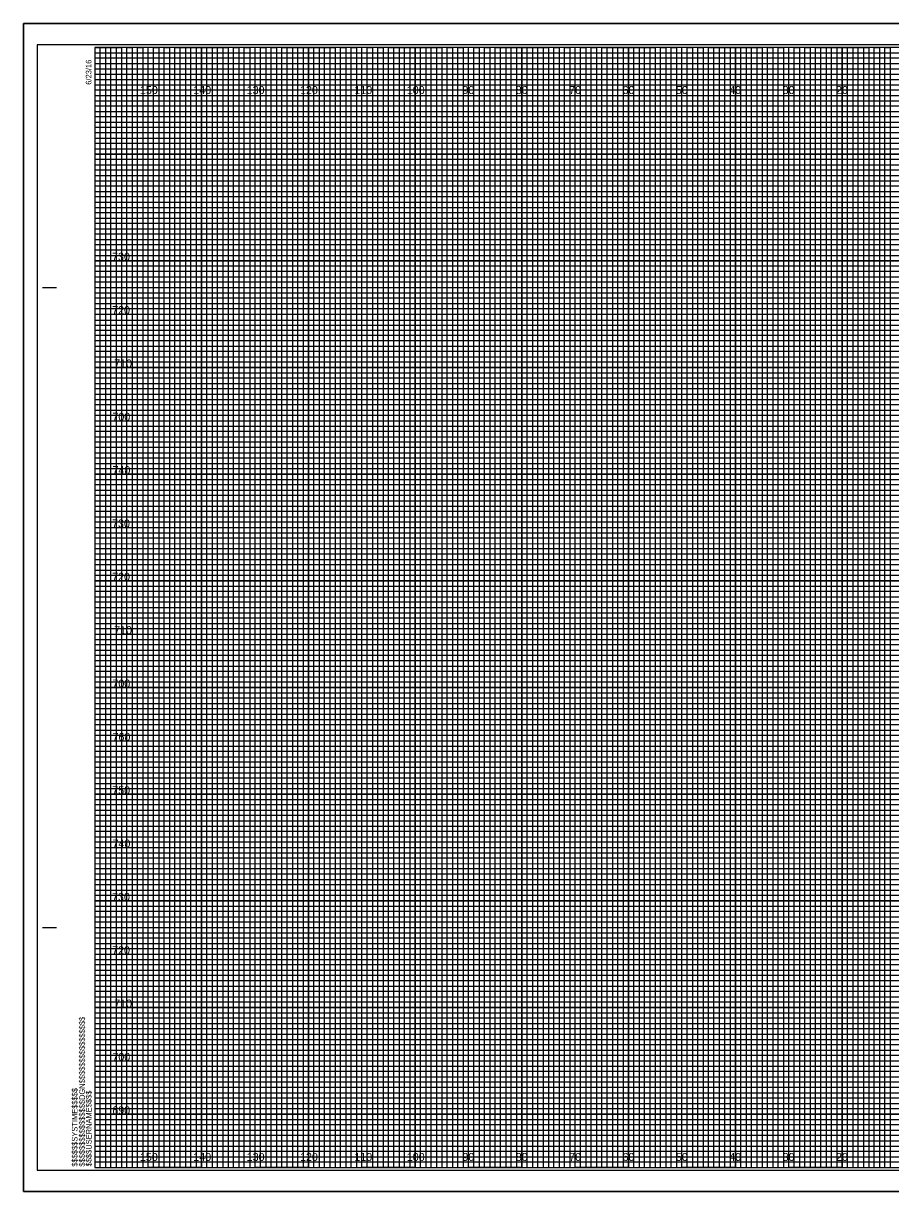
# Model space of a CAD drawing. Extents: x -397 to 323, y -4 to 654.
# Drawn here: x -13.4 to 149.1, y 215.5 to 434.5 of the extents above; entities that cross this region are included whole.
import ezdxf

# ---------------------------------------------------------------- set-up
doc = ezdxf.new("R2010")
doc.units = 0
for name, color, linetype in [('Default', 7, 'Continuous'), ('Prop XS Elevation Labels', 7, 'Continuous'), ('Prop XS Offset Labels', 7, 'Continuous'), ('Sheet Cross Section CELL', 7, 'Continuous'), ('Sheet Cross Section Grid Major CELL', 7, 'Continuous'), ('Sheet Cross Section Grid Middle CELL', 7, 'Continuous'), ('Sheet Cross Section Grid Minor 1 CELL', 7, 'Continuous'), ('Sheet Cross Section Grid Minor 2 CELL', 7, 'Continuous'), ('Sheet Cutting Line CELL', 7, 'Continuous'), ('Sheet DOT Grid CELL', 7, 'Continuous'), ('Sheet Plot Border Inside CELL', 7, 'Continuous'), ('Sheet Plot Border Outside CELL', 7, 'Continuous')]:
    doc.layers.add(name, color=color, linetype=linetype)

msp = doc.modelspace()

# ---------------------------------------------------------------- linework, layer by layer
at = {"layer": 'Default'}
msp.add_lwpolyline([(323.3, 215.5), (-13.4, 215.5), (-13.4, 434.5), (323.3, 434.5)], close=True, dxfattribs=at)
at = {"layer": 'Sheet Cross Section CELL'}
for p, q in [((-9.8, 385), (-7.3, 385)), ((-9.7, 385), (-7.2, 385)), ((-9.8, 265), (-7.3, 265)), ((-9.7, 265), (-7.2, 265)), ((0, 220), (0, 220)), ((0, 220), (0, 220)), ((0, 220), (0, 220)), ((0, 220), (0, 220)), ((0, 220), (0, 220)), ((0, 220), (0, 220)), ((0, 220), (0, 220))]:
    msp.add_line(p, q, dxfattribs=at)
msp.add_lwpolyline([(320, 430), (0, 430), (0, 220), (320, 220)], close=True, dxfattribs=at)
at = {"layer": 'Sheet Cross Section Grid Major CELL'}
for p, q in [((10, 430), (0, 430)), ((10, 220), (10, 430)), ((30, 430), (20, 430)), ((20, 430), (20, 220)), ((30, 220), (30, 430)), ((50, 430), (40, 430)), ((40, 430), (40, 220)), ((50, 220), (50, 430)), ((70, 430), (60, 430)), ((60, 430), (60, 220)), ((70, 220), (70, 430)), ((90, 430), (80, 430)), ((80, 430), (80, 220)), ((90, 220), (90, 430)), ((110, 430), (100, 430)), ((100, 430), (100, 220)), ((110, 220), (110, 430)), ((130, 430), (120, 430)), ((120, 430), (120, 220)), ((130, 220), (130, 430)), ((150, 430), (140, 430)), ((140, 430), (140, 220)), ((20, 220), (10, 220)), ((40, 220), (30, 220)), ((60, 220), (50, 220)), ((80, 220), (70, 220)), ((100, 220), (90, 220)), ((120, 220), (110, 220)), ((140, 220), (130, 220))]:
    msp.add_line(p, q, dxfattribs=at)
for points in [[(0, 420), (320, 420), (320, 410), (0, 410)], [(0, 400), (320, 400), (320, 390), (0, 390)], [(0, 380), (320, 380), (320, 370), (0, 370)], [(0, 360), (320, 360), (320, 350), (0, 350)], [(0, 340), (320, 340), (320, 330), (0, 330)], [(0, 320), (320, 320), (320, 310), (0, 310)], [(0, 300), (320, 300), (320, 290), (0, 290)], [(0, 280), (320, 280), (320, 270), (0, 270)], [(0, 260), (320, 260), (320, 250), (0, 250)], [(0, 240), (320, 240), (320, 230), (0, 230)]]:
    msp.add_lwpolyline(points, dxfattribs=at)
at = {"layer": 'Sheet Cross Section Grid Middle CELL'}
for points in [[(0, 430), (5, 430), (5, 220), (15, 220), (15, 430), (25, 430), (25, 220), (35, 220), (35, 430), (45, 430), (45, 220), (55, 220), (55, 430), (65, 430), (65, 220), (75, 220), (75, 430), (85, 430), (85, 220), (95, 220), (95, 430), (105, 430), (105, 220), (115, 220), (115, 430), (125, 430), (125, 220), (135, 220), (135, 430), (145, 430), (145, 220), (155, 220)], [(0, 425), (275, 425)], [(0, 405), (320, 405), (320, 415), (0, 415)], [(0, 385), (320, 385), (320, 395), (0, 395)], [(0, 365), (320, 365), (320, 375), (0, 375)], [(0, 345), (320, 345), (320, 355), (0, 355)], [(0, 325), (320, 325), (320, 335), (0, 335)], [(0, 305), (320, 305), (320, 315), (0, 315)], [(0, 285), (320, 285), (320, 295), (0, 295)], [(0, 265), (320, 265), (320, 275), (0, 275)], [(0, 245), (320, 245), (320, 255), (0, 255)], [(0, 225), (320, 225), (320, 235), (0, 235)]]:
    msp.add_lwpolyline(points, dxfattribs=at)
at = {"layer": 'Sheet Cross Section Grid Minor 1 CELL'}
for p, q in [((0, 429), (260, 429)), ((260, 427.98), (0, 427.98)), ((0, 427.98), (0, 427)), ((0, 427), (260, 427)), ((260, 425.89), (0, 425.89)), ((0, 425.89), (0, 424)), ((0, 424), (320, 424))]:
    msp.add_line(p, q, dxfattribs=at)
for points in [[(0, 423), (270, 423), (320, 423), (320, 422), (0, 422)], [(0, 421), (320, 421), (320, 419), (0, 419)], [(0, 418), (320, 418), (320, 417), (0, 416.98)], [(0, 416), (320, 416), (320, 414), (0, 414)], [(0, 413), (320, 413), (320, 412), (0, 412)], [(0, 411), (320, 411), (320, 409), (0, 409)], [(0, 408), (320, 408), (320, 407), (0, 407)], [(0, 406), (320, 406), (320, 404), (0, 404)], [(0, 403), (320, 403), (320, 402), (0, 402)], [(0, 401), (320, 401), (320, 399), (0, 399)], [(0, 398), (320, 398), (320, 397), (0, 397)], [(0, 396), (320, 396), (320, 393.95), (320, 393), (320, 392), (0, 392)], [(0, 394), (320, 394), (320, 393), (0, 393)], [(0, 391), (320, 391), (320, 389), (0, 389.03)], [(0, 389.03), (320, 389), (320, 388), (0, 388)], [(0, 387), (320, 387), (320, 386), (0, 386)], [(0, 384), (320, 384), (320, 383), (0, 383)], [(0, 382), (320, 382), (320, 381), (0, 381)], [(-0.07, 378.89), (320, 378.89), (320, 377.88), (-0.07, 377.88)], [(0, 377), (320, 377), (320, 376), (0, 376)], [(0, 374), (320, 374), (320, 373), (0, 373)], [(0, 372), (320, 372), (320, 371), (0, 371)], [(0, 369), (320, 369), (320, 368), (0, 368)], [(0, 367), (320, 367), (320, 366), (0, 366)], [(0, 364), (320, 364), (320, 363), (0, 363)], [(0, 362), (320, 362), (320, 361), (0, 361)], [(0, 359), (320, 359), (319.99, 357.98), (0, 358)], [(0, 357), (320, 357), (320, 356), (0, 356)], [(0, 354), (320, 354), (320, 353), (0, 353)], [(0, 352), (320, 352), (320, 351), (0, 351)], [(0, 349), (320, 349), (320, 348), (0, 348)], [(0, 347), (320, 347), (320, 346), (0, 346)], [(0, 344), (320, 344), (320, 343), (0, 343)], [(0, 342), (320, 342), (320, 341), (0, 341)], [(0, 339), (320, 339), (320, 338), (0, 338)], [(0, 336.99), (320.07, 336.91), (320, 336), (0, 336)], [(0, 334), (320, 334), (320, 333), (0, 333)], [(0, 332), (320, 332), (320, 331), (0, 331)], [(0, 329), (320, 329), (320, 328), (0, 328)], [(0, 327), (320, 327), (320, 326), (0, 326)], [(0, 324), (320, 324), (320, 323), (0, 323)], [(0, 322), (320, 322), (320, 321), (0, 321)], [(0, 319), (320, 319), (320, 318), (0, 318)], [(0, 317), (320, 317), (320, 316), (0, 316)], [(0, 314), (320, 314), (320, 313), (0, 313)], [(0, 312), (320, 312), (320, 311), (0, 311)], [(0, 309), (320, 309), (320, 308), (0, 308)], [(0, 307), (320, 307), (320, 306), (0, 306)], [(0, 304), (320, 304), (320, 303), (0, 303)], [(0, 302), (320, 302), (320, 301), (0, 301)], [(0, 299), (320, 299), (319.99, 297.98), (0, 298)], [(0, 297), (320, 297), (320, 296), (0, 296)], [(0, 294), (320, 294), (320, 293), (0, 293)], [(0, 292), (320, 292), (320, 291), (0, 291)], [(0, 289), (320, 289), (320, 288), (0, 288)], [(0, 287), (320, 287), (320, 286), (0, 286)], [(0, 284), (320, 284), (320, 283), (0, 283)], [(0, 282), (320, 282), (320, 281), (0, 281)], [(0, 279), (320, 279), (320, 278), (0, 278)], [(0, 276.99), (320.07, 276.91), (320, 276), (0, 276)], [(0, 274), (320, 274), (320, 273), (0, 273)], [(0, 272), (320, 272), (320, 271), (0, 271)], [(0, 269), (320, 269), (320, 268), (0, 268)], [(0, 267), (320, 267), (320, 266), (0, 266)], [(0, 264), (320, 264), (320, 263), (0, 263)], [(0, 262), (320, 262), (320, 261), (0, 261)], [(0, 259), (320, 259), (320, 258), (0, 258)], [(0, 257), (320, 257), (320, 256), (0, 256)], [(0, 254), (320, 254), (320, 253), (0, 253)], [(0, 252), (320, 252), (320, 251), (0, 251)], [(0, 249), (320, 249), (320, 248), (0, 248)], [(0, 247), (320, 247), (320, 246), (0, 246)], [(0, 244), (320, 244), (320, 243), (0, 243)], [(0, 242), (320, 242), (320, 241), (0, 241)], [(0, 239), (320, 239), (320, 238), (0, 238)], [(0, 237), (320, 237), (320, 236), (0, 236)], [(0, 234), (320, 234), (320, 233), (0, 233)], [(0, 232), (320, 232), (320, 231), (0, 231)], [(0, 229), (320, 229), (320, 228), (0, 228)], [(0, 227), (320, 227), (320, 226), (0, 226)], [(0, 224), (320, 224), (320, 223), (0, 223)], [(0, 222), (320, 222), (320, 221), (0, 221)]]:
    msp.add_lwpolyline(points, dxfattribs=at)
at = {"layer": 'Sheet Cross Section Grid Minor 2 CELL'}
for points in [[(0, 220), (1, 220), (1, 430), (2, 430), (2, 220)], [(2, 220), (3, 220), (3, 430), (4, 430), (4, 220)], [(5, 220), (6, 220), (6, 430), (7, 430), (7, 220)], [(7, 220), (8, 220), (8, 430), (9, 430), (9, 220)], [(10, 220), (11, 220), (11, 430), (12, 430), (12, 220)], [(12, 220), (13, 220), (13, 430), (14, 430), (14, 220)], [(15, 220), (16, 220), (16, 430), (17, 430), (17, 220)], [(17, 220), (18, 220), (18, 430), (19, 430), (19, 220)], [(20, 220), (21, 220), (21, 430), (22, 430), (22, 220)], [(22, 220), (23, 220), (23, 430), (24, 430), (24, 220)], [(25, 220), (26, 220), (26, 430), (27, 430), (27, 220)], [(27, 220), (28, 220), (28, 430), (29, 430), (29, 220)], [(30, 220), (31, 220), (31, 430), (32, 430), (32, 220)], [(32, 220), (33, 220), (33, 430), (34, 430), (34, 220)], [(35, 220), (36, 220), (36, 430), (37, 430), (37, 220)], [(37, 220), (38, 220), (38, 430), (39, 430), (39, 220)], [(40, 220), (41, 220), (41, 430), (42, 430), (42, 220)], [(42, 220), (43, 220), (43, 430), (44, 430), (44, 220)], [(45, 220), (46, 220), (46, 430), (47, 430), (47, 220)], [(47, 220), (48, 220), (48, 430), (49, 430), (49, 220)], [(50, 220), (51, 220), (51, 430), (52, 430), (52, 220)], [(52, 220), (53, 220), (53, 430), (54, 430), (54, 220)], [(55, 220), (56, 220), (56, 430), (57, 430), (57, 220)], [(57, 220), (58, 220), (58, 430), (59, 430), (59, 220)], [(60, 220), (61, 220), (61, 430), (62, 430), (62, 220)], [(62, 220), (63, 220), (63, 430), (64, 430), (64, 220)], [(65, 220), (66, 220), (66, 430), (67, 430), (67, 220)], [(67, 220), (68, 220), (68, 430), (69, 430), (69, 220)], [(70, 220), (71, 220), (71, 430), (72, 430), (72, 220)], [(72, 220), (73, 220), (73, 430), (74, 430), (74, 220)], [(75, 220), (76, 220), (76, 430), (77, 430), (77, 220)], [(77, 220), (78, 220), (78, 430), (79, 430), (79, 220)], [(80, 220), (81, 220), (81, 430), (82, 430), (82, 220)], [(82, 220), (83, 220), (83, 430), (84, 430), (84, 220)], [(85, 220), (86, 220), (86, 430), (87, 430), (87, 220)], [(87, 220), (88, 220), (88, 430), (89, 430), (89, 220)], [(90, 220), (91, 220), (91, 430), (92, 430), (92, 220)], [(92, 220), (93, 220), (93, 430), (94, 430), (94, 220)], [(95, 220), (96, 220), (96, 430), (97, 430), (97, 220)], [(97, 220), (98, 220), (98, 430), (99, 430), (99, 220)], [(100, 220), (101, 220), (101, 430), (102, 430), (102, 220)], [(102, 220), (103, 220), (103, 430), (104, 430), (104, 220)], [(105, 220), (106, 220), (106, 430), (107, 430), (107, 220)], [(107, 220), (108, 220), (108, 430), (109, 430), (109, 220)], [(110, 220), (111, 220), (111, 430), (112, 430), (112, 220)], [(112, 220), (113, 220), (113, 430), (114, 430), (114, 220)], [(115, 220), (116, 220), (116, 430), (117, 430), (117, 220)], [(117, 220), (118, 220), (118, 430), (119, 430), (119, 220)], [(120, 220), (121, 220), (121, 430), (122, 430), (122, 220)], [(122, 220), (123, 220), (123, 430), (124, 430), (124, 220)], [(125, 220), (126, 220), (126, 430), (127, 430), (127, 220)], [(127, 220), (128, 220), (128, 430), (129, 430), (129, 220)], [(130, 220), (131, 220), (131, 430), (132, 430), (132, 220)], [(132, 220), (133, 220), (133, 430), (134, 430), (134, 220)], [(135, 220), (136, 220), (136, 430), (137, 430), (137, 220)], [(137, 220), (138, 220), (138, 430), (139, 430), (139, 220)], [(140, 220), (141, 220), (141, 430), (142, 430), (142, 220)], [(142, 220), (143, 220), (143, 430), (144, 430), (144, 220)], [(145, 220), (146, 220), (146, 430), (147, 430), (147, 220)], [(147, 220), (148, 220), (148, 430), (149, 430), (149, 220)]]:
    msp.add_lwpolyline(points, dxfattribs=at)
at = {"layer": 'Sheet Cutting Line CELL'}
for p, q in [((323.3, 434.5), (-13.4, 434.5)), ((-13.4, 434.5), (-13.4, 215.5)), ((-13.4, 215.5), (323.3, 215.5))]:
    msp.add_line(p, q, dxfattribs=at)
at = {"layer": 'Sheet DOT Grid CELL'}
for p, q in [((10, 220), (10, 430)), ((20, 220), (20, 430)), ((30, 220), (30, 430)), ((40, 220), (40, 430)), ((50, 220), (50, 430)), ((60, 220), (60, 430)), ((70, 220), (70, 430)), ((80, 220), (80, 430)), ((90, 220), (90, 430)), ((100, 220), (100, 430)), ((110, 220), (110, 430)), ((120, 220), (120, 430)), ((130, 220), (130, 430)), ((140, 220), (140, 430)), ((0, 420), (320, 420)), ((0, 410), (320, 410)), ((0, 400), (320, 400)), ((0, 390), (320, 390)), ((0, 380), (320, 380)), ((0, 370), (320, 370)), ((0, 360), (320, 360)), ((0, 350), (320, 350)), ((0, 340), (320, 340)), ((0, 330), (320, 330)), ((0, 320), (320, 320)), ((0, 310), (320, 310)), ((0, 300), (320, 300)), ((0, 290), (320, 290)), ((0, 280), (320, 280)), ((0, 270), (320, 270)), ((0, 260), (320, 260)), ((0, 250), (320, 250)), ((0, 240), (320, 240)), ((0, 230), (320, 230))]:
    msp.add_line(p, q, dxfattribs=at)
at = {"layer": 'Sheet Plot Border Inside CELL'}
msp.add_lwpolyline([(-10.8, 219.5), (322.4, 219.5), (322.4, 430.5), (-10.8, 430.5)], close=True, dxfattribs=at)
at = {"layer": 'Sheet Plot Border Outside CELL'}
msp.add_lwpolyline([(-13.4, 215.5), (323.3, 215.5), (323.3, 434.5), (-13.4, 434.5)], close=True, dxfattribs=at)

# ---------------------------------------------------------------- texts
at = {"layer": 'Prop XS Elevation Labels'}
for s, p in [('730', (3.22, 390)), ('720', (3.23, 380)), ('710', (3.61, 370)), ('700', (3.28, 360)), ('740', (3.3, 350)), ('730', (3.22, 340)), ('720', (3.23, 330)), ('710', (3.61, 320)), ('700', (3.28, 310)), ('760', (3.3, 300)), ('750', (3.25, 290)), ('740', (3.3, 280)), ('730', (3.22, 270)), ('720', (3.23, 260)), ('710', (3.61, 250)), ('700', (3.28, 240)), ('690', (3.26, 230))]:
    msp.add_text(s, height=1.5, dxfattribs=at).set_placement(p)
at = {"layer": 'Prop XS Offset Labels'}
for s, p in [('150', (8.44, 421.25)), ('140', (18.44, 421.25)), ('130', (28.44, 421.25)), ('120', (38.44, 421.25)), ('110', (48.62, 421.25)), ('100', (58.44, 421.25)), ('90', (68.86, 421.25)), ('80', (78.86, 421.25)), ('70', (88.86, 421.25)), ('60', (98.86, 421.25)), ('50', (108.86, 421.25)), ('40', (118.86, 421.25)), ('30', (128.86, 421.25)), ('20', (138.86, 421.25)), ('150', (8.44, 221.25)), ('140', (18.44, 221.25)), ('130', (28.44, 221.25)), ('120', (38.44, 221.25)), ('110', (48.62, 221.25)), ('100', (58.44, 221.25)), ('90', (68.86, 221.25)), ('80', (78.86, 221.25)), ('70', (88.86, 221.25)), ('60', (98.86, 221.25)), ('50', (108.86, 221.25)), ('40', (118.86, 221.25)), ('30', (128.86, 221.25)), ('20', (138.86, 221.25))]:
    msp.add_text(s, height=1.5, dxfattribs=at).set_placement(p)
at = {"layer": 'Sheet Cross Section CELL'}
for s, p in [('6/23/16', (-0.65, 423)), ('$$$$$$$$$$$$$$$$DGN$$$$$$$$$$$$$$$$', (-1.88, 220.18)), ('$$$$$$SYSTIME$$$$$', (-3.26, 220.18)), ('$$$$USERNAME$$$$', (-0.62, 220.23))]:
    msp.add_text(s, height=1.05, rotation=90, dxfattribs=at).set_placement(p)

doc.saveas('drawing.dxf')
